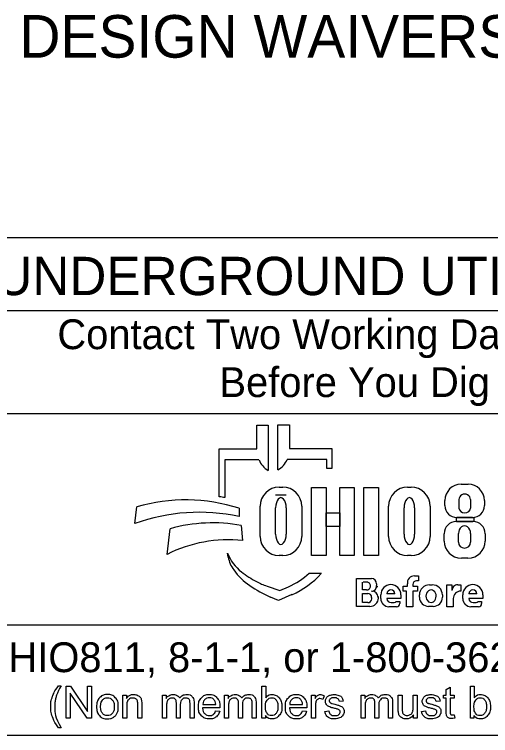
# Model space of a CAD drawing. Extents: x 0 to 34, y 0 to 22.
# Drawn here: x 2.596 to 4.831, y 2.143 to 5.529 of the extents above; entities that cross this region are included whole.
import ezdxf

# ---------------------------------------------------------------- set-up
doc = ezdxf.new("R2010")
doc.units = 0
doc.layers.add('SH_Data', color=7, linetype='Continuous')
doc.layers.add('SH_Text', color=7, linetype='Continuous')

msp = doc.modelspace()

# ---------------------------------------------------------------- linework, layer by layer
at = {"layer": 'SH_Data'}
for p, q in [((6.6275, 4.4803), (2.3775, 4.4803)), ((2.3775, 4.1387), (6.6275, 4.1387)), ((2.3775, 3.6553), (6.6275, 3.6553)), ((6.6275, 2.6607), (2.3775, 2.6607)), ((6.6275, 2.1428), (2.3775, 2.1428))]:
    msp.add_line(p, q, dxfattribs=at)
at = {"layer": 'SH_Text'}
for p, q in [((3.7335, 3.4883), (3.7335, 3.5998)), ((3.7335, 3.5998), (3.7872, 3.5998)), ((3.7872, 3.5998), (3.7872, 3.3877)), ((3.8329, 3.39), (3.8329, 3.6021)), ((3.8329, 3.6021), (3.8865, 3.6021)), ((3.8865, 3.6021), (3.8865, 3.4906)), ((3.5576, 3.2644), (3.5576, 3.4883)), ((3.5576, 3.4883), (3.7335, 3.4883)), ((3.8865, 3.4906), (4.0857, 3.4906)), ((4.0857, 3.4906), (4.0857, 3.3968)), ((3.5828, 3.4369), (3.5828, 3.26)), ((3.7439, 3.4369), (3.5828, 3.4369)), ((4.0625, 3.4392), (3.8761, 3.4392)), ((4.0625, 3.3968), (4.0625, 3.4392)), ((4.0857, 3.3968), (4.0625, 3.3968)), ((4.6931, 3.3231), (4.7258, 3.3231)), ((3.8385, 3.3091), (3.8551, 3.3091)), ((4.4416, 3.3091), (4.4581, 3.3091)), ((3.8718, 3.2721), (3.822, 3.2721)), ((4.683, 3.2111), (4.683, 3.2504)), ((4.7371, 3.2504), (4.7371, 3.2111)), ((3.7491, 3.0776), (3.7491, 3.2196)), ((3.9445, 3.2196), (3.9445, 3.0776)), ((4.3521, 3.0776), (4.3521, 3.2196)), ((4.5476, 3.2196), (4.5476, 3.0776)), ((4.6168, 3.2225), (4.6168, 3.2468)), ((4.8022, 3.2468), (4.8022, 3.2225)), ((3.1602, 3.1381), (3.1696, 3.2162)), ((3.6509, 3.2097), (3.6509, 3.1709)), ((3.822, 3.089), (3.822, 3.2114)), ((3.8718, 3.2114), (3.8718, 3.089)), ((4.425, 3.089), (4.425, 3.2114)), ((4.4748, 3.2114), (4.4748, 3.089)), ((4.7462, 3.1665), (4.6728, 3.1665)), ((3.6608, 3.1291), (3.6671, 3.0582)), ((4.671, 3.1482), (4.7483, 3.1482)), ((3.312, 2.9936), (3.3267, 3.1137)), ((4.6131, 3.0563), (4.6131, 3.0903)), ((4.6806, 3.0503), (4.6806, 3.0912)), ((4.7374, 3.0912), (4.7374, 3.0503)), ((4.8062, 3.0903), (4.8062, 3.0563)), ((3.5997, 2.9807), (3.5967, 2.9986)), ((3.8551, 2.9882), (3.8385, 2.9882)), ((4.4581, 2.9882), (4.4416, 2.9882)), ((4.7252, 2.9753), (4.6941, 2.9753)), ((3.98, 2.9048), (4.0375, 2.9048)), ((4.2013, 2.749), (4.2013, 2.8798)), ((4.2013, 2.8798), (4.2725, 2.8798)), ((4.4739, 2.8926), (4.4934, 2.8926)), ((4.4934, 2.8926), (4.4934, 2.8696)), ((3.7816, 2.8444), (3.841, 2.8239)), ((4.2293, 2.8263), (4.2293, 2.8632)), ((4.2545, 2.8632), (4.2332, 2.8632)), ((4.2963, 2.856), (4.2963, 2.8481)), ((4.4213, 2.8212), (4.4213, 2.8442)), ((4.4213, 2.8442), (4.4406, 2.8442)), ((4.4406, 2.8442), (4.4406, 2.8546)), ((4.4667, 2.8526), (4.4667, 2.8442)), ((4.4667, 2.8442), (4.4883, 2.8442)), ((4.4934, 2.8691), (4.4832, 2.8691)), ((4.4883, 2.8442), (4.4883, 2.8212)), ((4.5451, 2.8508), (4.5573, 2.8508)), ((4.6254, 2.7478), (4.6254, 2.8505)), ((4.6254, 2.8505), (4.6499, 2.8505)), ((4.6499, 2.8505), (4.6499, 2.8237)), ((4.6772, 2.8505), (4.691, 2.8505)), ((4.691, 2.8505), (4.691, 2.8209)), ((3.841, 2.8239), (3.8821, 2.8417)), ((4.2487, 2.8263), (4.2293, 2.8263)), ((4.4362, 2.8212), (4.4213, 2.8212)), ((4.4362, 2.7478), (4.4362, 2.8212)), ((4.4883, 2.8212), (4.4667, 2.8212)), ((4.4667, 2.8212), (4.4667, 2.7478)), ((3.835, 2.7769), (3.7976, 2.7934)), ((3.8983, 2.8044), (3.835, 2.7769)), ((4.2293, 2.7669), (4.2293, 2.8097)), ((4.2293, 2.8097), (4.2548, 2.8097)), ((4.2729, 2.7916), (4.2729, 2.7853)), ((4.3043, 2.7887), (4.3043, 2.7884)), ((4.3159, 2.7858), (4.3159, 2.8042)), ((4.3824, 2.8082), (4.3439, 2.8082)), ((4.4104, 2.7866), (4.344, 2.7866)), ((4.4104, 2.8042), (4.4104, 2.7866)), ((4.4973, 2.7922), (4.4973, 2.8029)), ((4.6051, 2.8029), (4.6051, 2.7922)), ((4.6559, 2.786), (4.6559, 2.7478)), ((4.7008, 2.7858), (4.7008, 2.8042)), ((4.7674, 2.8082), (4.7288, 2.8082)), ((4.7953, 2.7866), (4.7289, 2.7866)), ((4.7953, 2.8042), (4.7953, 2.7866)), ((4.265, 2.749), (4.2013, 2.749)), ((4.2546, 2.7669), (4.2293, 2.7669)), ((4.3892, 2.7478), (4.3538, 2.7478)), ((4.3649, 2.7673), (4.379, 2.7673)), ((4.3876, 2.7729), (4.4045, 2.7729)), ((4.4045, 2.7729), (4.4045, 2.7631)), ((4.4667, 2.7478), (4.4362, 2.7478)), ((4.5623, 2.7494), (4.5401, 2.7494)), ((4.6559, 2.7478), (4.6254, 2.7478)), ((4.7742, 2.7478), (4.7388, 2.7478)), ((4.7498, 2.7673), (4.7639, 2.7673)), ((4.7725, 2.7729), (4.7894, 2.7729)), ((4.7894, 2.7729), (4.7894, 2.7631))]:
    msp.add_line(p, q, dxfattribs=at)
for points in [[(3.991, 3.3081), (4.0589, 3.3081), (4.0589, 2.9881), (3.991, 2.9881)], [(4.1231, 3.3081), (4.1911, 3.3081), (4.1911, 2.9881), (4.1231, 2.9881)], [(4.2364, 3.3081), (4.3052, 3.3081), (4.3052, 2.9881), (4.2364, 2.9881)], [(4.0589, 3.1882), (4.1231, 3.1882), (4.1231, 3.1242), (4.0589, 3.1242)], [(4.6706, 3.1665), (4.7523, 3.1665), (4.7523, 3.1481), (4.6706, 3.1481)]]:
    msp.add_lwpolyline(points, close=True, dxfattribs=at)
for points in [[(2.8021, 2.3766), (2.8153, 2.3766)], [(2.8389, 2.2239), (2.8389, 2.3741), (2.8592, 2.3741), (2.9382, 2.2561), (2.9382, 2.3741), (2.9572, 2.3741), (2.9572, 2.2239), (2.9369, 2.2239), (2.8579, 2.3419), (2.8579, 2.2239), (2.8389, 2.2239)], [(3.7743, 2.2239), (3.7573, 2.2239), (3.7573, 2.3741), (3.7757, 2.3741), (3.7757, 2.3206)], [(4.6233, 2.2558), (4.6233, 2.3185), (4.6097, 2.3185), (4.6097, 2.3328), (4.6233, 2.3328), (4.6233, 2.3597), (4.6417, 2.3708), (4.6417, 2.3328), (4.6601, 2.3328), (4.6601, 2.3185), (4.6417, 2.3185), (4.6417, 2.2547)], [(4.7534, 2.2239), (4.7363, 2.2239), (4.7363, 2.3741), (4.7548, 2.3741), (4.7548, 2.3206)], [(3.1048, 2.2239), (3.1048, 2.3328), (3.1214, 2.3328), (3.1214, 2.3173)], [(3.2912, 2.2239), (3.2912, 2.3328), (3.3077, 2.3328), (3.3077, 2.3174)], [(3.5826, 2.2239), (3.5826, 2.3328), (3.5991, 2.3328), (3.5991, 2.3174)], [(3.9904, 2.2239), (3.9904, 2.3328), (4.007, 2.3328), (4.007, 2.3163)], [(4.0495, 2.3293), (4.043, 2.3122)], [(4.1394, 2.3046), (4.1213, 2.3022)], [(4.2236, 2.2239), (4.2236, 2.3328), (4.2401, 2.3328), (4.2401, 2.3174)], [(4.3979, 2.2654), (4.3979, 2.3328), (4.4164, 2.3328), (4.4164, 2.2724)], [(4.4676, 2.2745), (4.4676, 2.3328), (4.4861, 2.3328), (4.4861, 2.2239), (4.4696, 2.2239)], [(4.594, 2.3046), (4.5759, 2.3022)], [(3.1233, 2.2833), (3.1233, 2.2239), (3.1048, 2.2239)], [(3.1932, 2.2908), (3.1932, 2.2239), (3.1748, 2.2239), (3.1748, 2.2901)], [(3.3097, 2.2803), (3.3097, 2.2239), (3.2912, 2.2239)], [(3.3743, 2.2871), (3.3743, 2.2239), (3.3559, 2.2239), (3.3559, 2.2946)], [(3.4388, 2.2986), (3.4388, 2.2239), (3.4203, 2.2239), (3.4203, 2.2924)], [(3.56, 2.2736), (3.4788, 2.2736)], [(3.4799, 2.2887), (3.5406, 2.2887)], [(3.601, 2.2803), (3.601, 2.2239), (3.5826, 2.2239)], [(3.6657, 2.2871), (3.6657, 2.2239), (3.6473, 2.2239), (3.6473, 2.2946)], [(3.7301, 2.2986), (3.7301, 2.2239), (3.7117, 2.2239), (3.7117, 2.2924)], [(3.968, 2.2736), (3.8868, 2.2736)], [(3.8879, 2.2887), (3.9486, 2.2887)], [(4.0088, 2.2809), (4.0088, 2.2239), (3.9904, 2.2239)], [(4.242, 2.2803), (4.242, 2.2239), (4.2236, 2.2239)], [(4.3067, 2.2871), (4.3067, 2.2239), (4.2883, 2.2239), (4.2883, 2.2946)], [(4.3711, 2.2986), (4.3711, 2.2239), (4.3527, 2.2239), (4.3527, 2.2924)], [(3.5404, 2.2591), (3.5595, 2.2567)], [(3.7743, 2.2375), (3.7743, 2.2239)], [(3.9484, 2.2591), (3.9675, 2.2567)], [(4.053, 2.2564), (4.0712, 2.2593)], [(4.4696, 2.2239), (4.4696, 2.24)], [(4.5076, 2.2564), (4.5258, 2.2593)], [(4.6601, 2.2404), (4.6628, 2.2241)], [(4.7534, 2.2375), (4.7534, 2.2239)], [(2.8153, 2.1798), (2.8021, 2.1798)]]:
    msp.add_lwpolyline(points, dxfattribs=at)
for centre, radius, start, end in [((3.8353, 3.4736), 0.0985, 201.9296, 240.7469), ((3.7847, 3.476), 0.0985, 299.2531, 338.0704), ((4.6931, 3.2468), 0.0763, 90, 180), ((4.7258, 3.2468), 0.0763, 0, 90), ((3.8385, 3.2196), 0.0895, 90, 180), ((3.8551, 3.2196), 0.0895, 0, 90), ((4.4416, 3.2196), 0.0895, 90, 180), ((4.4581, 3.2196), 0.0895, 0, 90), ((3.4295, 2.4554), 0.8191, 79.2074, 81.0007), ((3.3997, 2.4302), 0.8191, 72.1402, 106.3144), ((4.6728, 3.2225), 0.056, 180, 270), ((4.7462, 3.2225), 0.056, 270, 0), ((3.4628, 2.2991), 0.8919, 77.8238, 109.8274), ((3.5267, 2.4094), 0.7322, 79.44, 105.8467), ((4.671, 3.0903), 0.0579, 90, 180), ((4.7483, 3.0903), 0.0579, 0, 90), ((3.5987, 2.4262), 0.6357, 83.8248, 116.8021), ((3.8385, 3.0776), 0.0895, 180, 270), ((3.8551, 3.0776), 0.0895, 270, 0), ((4.4416, 3.0776), 0.0895, 180, 270), ((4.4581, 3.0776), 0.0895, 270, 0), ((4.6941, 3.0563), 0.081, 180, 270), ((4.7252, 3.0563), 0.081, 270, 0), ((3.7841, 3.0707), 0.2008, 201.0457, 232.5314), ((3.741, 3.0048), 0.1433, 189.6817, 216.0884), ((3.8747, 3.1022), 0.3088, 216.0884, 235.7167), ((3.9766, 3.3219), 0.5173, 232.5314, 241.794), ((3.7387, 3.1722), 0.3602, 293.4582, 312.0712), ((3.7387, 3.1722), 0.401, 293.4582, 317.8286), ((4.2725, 2.856), 0.0238, 0, 90), ((4.4739, 2.859), 0.0335, 90, 187.5187), ((4.0412, 3.3465), 0.6044, 235.7167, 246.2325), ((3.8914, 3.1631), 0.3371, 241.794, 250.9821), ((4.2487, 2.845), 0.0187, 270, 2.0582), ((4.2505, 2.8463), 0.0169, 357.8325, 90), ((4.2721, 2.8453), 0.0243, 270, 6.6529), ((4.3631, 2.8042), 0.0473, 0, 180), ((4.4832, 2.8526), 0.0165, 90, 180), ((4.5451, 2.8029), 0.0478, 90, 180), ((4.5573, 2.8029), 0.0478, 0, 90), ((4.6768, 2.8237), 0.0269, 89.2449, 180), ((4.7481, 2.8042), 0.0473, 0, 180), ((4.2722, 2.7889), 0.0321, 4.0748, 90), ((4.2827, 2.8438), 0.0175, 347.4023, 0), ((4.3632, 2.8072), 0.0193, 2.9632, 177.0368), ((4.6908, 2.786), 0.0349, 89.6033, 180), ((4.7481, 2.8072), 0.0193, 2.9632, 177.0368), ((4.2546, 2.7853), 0.0184, 270, 0), ((4.2548, 2.7916), 0.0181, 0, 90), ((4.265, 2.7884), 0.0393, 270, 0), ((4.2714, 2.7887), 0.033, 0, 11.7502), ((4.3538, 2.7858), 0.038, 180, 270), ((4.3649, 2.7883), 0.021, 184.827, 270), ((4.5401, 2.7922), 0.0428, 180, 270), ((4.5623, 2.7922), 0.0428, 270, 0), ((4.7388, 2.7858), 0.038, 180, 270), ((4.7498, 2.7883), 0.021, 184.827, 270), ((4.379, 2.7767), 0.00938, 270, 335.9979), ((4.3892, 2.7631), 0.0152, 270, 0), ((4.7639, 2.7767), 0.00938, 270, 335.9979), ((4.7742, 2.7631), 0.0152, 270, 0)]:
    msp.add_arc(centre, radius, start, end, dxfattribs=at)
for centre, major_axis, ratio, start_param, end_param in [((3.8469, 3.2114), (0, 0.0484), 0.514403, 4.712389, 7.853982), ((4.4499, 3.2114), (0, 0.0484), 0.514403, 4.712389, 7.853982), ((4.71, 3.2504), (0.0271, 0), 0.969373, 0, 3.141593), ((4.71, 3.2111), (0.0271, 0), 0.818453, 3.141593, 6.283185), ((4.709, 3.0912), (0, 0.0358), 0.794529, 4.712389, 7.853982), ((3.8469, 3.089), (0, 0.0484), 0.514403, 1.570796, 4.712389), ((4.4499, 3.089), (0, 0.0484), 0.514403, 1.570796, 4.712389), ((4.709, 3.0503), (0.0284, 0), 0.959837, 3.141593, 6.283185), ((4.5517, 2.7976), (0, 0.029), 0.832186, 4.712389, 7.853982), ((4.5517, 2.7976), (0, 0.0302), 0.797287, 1.570796, 4.712389)]:
    msp.add_ellipse(centre, major_axis=major_axis, ratio=ratio, start_param=start_param, end_param=end_param, dxfattribs=at)
for points in [[(2.8021, 2.1798), (2.7869, 2.199), (2.7763, 2.2248), (2.7657, 2.2506), (2.7657, 2.2783), (2.7657, 2.3026), (2.7736, 2.325), (2.7829, 2.3509), (2.8021, 2.3766)], [(2.8153, 2.3766), (2.8029, 2.3553), (2.7989, 2.3462), (2.7927, 2.332), (2.7891, 2.3167), (2.7847, 2.2975), (2.7847, 2.2782), (2.7847, 2.2289), (2.8153, 2.1798)], [(2.9814, 2.2783), (2.9814, 2.3085), (2.9981, 2.3231), (3.0122, 2.3352), (3.0323, 2.3352), (3.0547, 2.3352), (3.069, 2.3205), (3.0832, 2.3058), (3.0832, 2.2799), (3.0832, 2.2589), (3.0769, 2.2469), (3.0706, 2.2348), (3.0586, 2.2282), (3.0466, 2.2215), (3.0323, 2.2215), (3.0095, 2.2215), (2.9954, 2.2362), (2.9814, 2.2508), (2.9814, 2.2783)], [(3.0003, 2.2783), (3.0003, 2.2574), (3.0094, 2.247), (3.0185, 2.2366), (3.0323, 2.2366), (3.046, 2.2366), (3.0551, 2.2471), (3.0642, 2.2575), (3.0642, 2.279), (3.0642, 2.2991), (3.0551, 2.3095), (3.0459, 2.3199), (3.0323, 2.3199), (3.0185, 2.3199), (3.0094, 2.3096), (3.0003, 2.2992), (3.0003, 2.2783)], [(3.1214, 2.3173), (3.1334, 2.3352), (3.156, 2.3352), (3.1659, 2.3352), (3.1741, 2.3316), (3.1823, 2.3281), (3.1864, 2.3224), (3.1905, 2.3166), (3.1922, 2.3087), (3.1932, 2.3036), (3.1932, 2.2908)], [(3.1748, 2.2901), (3.1748, 2.3013), (3.1726, 2.3069), (3.1705, 2.3125), (3.165, 2.3158), (3.1595, 2.3191), (3.1521, 2.3191), (3.1404, 2.3191), (3.1318, 2.3117), (3.1233, 2.3042), (3.1233, 2.2833)], [(3.3077, 2.3174), (3.3128, 2.3254), (3.3214, 2.3303), (3.3299, 2.3352), (3.3407, 2.3352), (3.3528, 2.3352), (3.3606, 2.3301), (3.3683, 2.3251), (3.3715, 2.3161), (3.3844, 2.3352), (3.4051, 2.3352), (3.4213, 2.3352), (3.43, 2.3262), (3.4388, 2.3172), (3.4388, 2.2986)], [(3.3559, 2.2946), (3.3559, 2.3069), (3.3514, 2.313), (3.3469, 2.3191), (3.3366, 2.3191), (3.3288, 2.3191), (3.3222, 2.315), (3.3156, 2.311), (3.3126, 2.3031), (3.3097, 2.2952), (3.3097, 2.2803)], [(3.4203, 2.2924), (3.4203, 2.3035), (3.4185, 2.3083), (3.4168, 2.3132), (3.412, 2.3162), (3.4073, 2.3191), (3.401, 2.3191), (3.3895, 2.3191), (3.3819, 2.3115), (3.3743, 2.3039), (3.3743, 2.2871)], [(3.5595, 2.2567), (3.555, 2.24), (3.5428, 2.2307), (3.5306, 2.2215), (3.5117, 2.2215), (3.4878, 2.2215), (3.4738, 2.2362), (3.4598, 2.2509), (3.4598, 2.2774), (3.4598, 2.3049), (3.474, 2.32), (3.4881, 2.3352), (3.5106, 2.3352), (3.5324, 2.3352), (3.5463, 2.3203), (3.5601, 2.3055), (3.5601, 2.2785), (3.5601, 2.2769), (3.56, 2.2736)], [(3.5406, 2.2887), (3.5394, 2.3025), (3.5337, 2.3094), (3.5249, 2.3201), (3.5108, 2.3201), (3.4981, 2.3201), (3.4894, 2.3115), (3.4808, 2.303), (3.4799, 2.2887)], [(3.5991, 2.3174), (3.6042, 2.3254), (3.6127, 2.3303), (3.6212, 2.3352), (3.6321, 2.3352), (3.6442, 2.3352), (3.6519, 2.3301), (3.6597, 2.3251), (3.6628, 2.3161), (3.6758, 2.3352), (3.6965, 2.3352), (3.7127, 2.3352), (3.7214, 2.3262), (3.7301, 2.3172), (3.7301, 2.2986)], [(3.6473, 2.2946), (3.6473, 2.3069), (3.6428, 2.313), (3.6383, 2.3191), (3.628, 2.3191), (3.6202, 2.3191), (3.6136, 2.315), (3.607, 2.311), (3.604, 2.3031), (3.601, 2.2952), (3.601, 2.2803)], [(3.7117, 2.2924), (3.7117, 2.3035), (3.7099, 2.3083), (3.7081, 2.3132), (3.7034, 2.3162), (3.6987, 2.3191), (3.6923, 2.3191), (3.6809, 2.3191), (3.6733, 2.3115), (3.6657, 2.3039), (3.6657, 2.2871)], [(3.7741, 2.2792), (3.7741, 2.2596), (3.7794, 2.2509), (3.7881, 2.2366), (3.8029, 2.2366), (3.815, 2.2366), (3.8238, 2.2471), (3.8326, 2.2576), (3.8326, 2.2784), (3.8326, 2.2998), (3.8241, 2.3099), (3.8157, 2.3201), (3.8038, 2.3201), (3.7917, 2.3201), (3.7829, 2.3096), (3.7741, 2.299), (3.7741, 2.2792)], [(3.7757, 2.3206), (3.7874, 2.3352), (3.8055, 2.3352), (3.8155, 2.3352), (3.8245, 2.3311), (3.8335, 2.3271), (3.8392, 2.3198), (3.845, 2.3124), (3.8483, 2.3021), (3.8516, 2.2918), (3.8516, 2.28), (3.8516, 2.252), (3.8378, 2.2368), (3.8239, 2.2215), (3.8046, 2.2215), (3.7853, 2.2215), (3.7743, 2.2375)], [(3.9675, 2.2567), (3.963, 2.24), (3.9508, 2.2307), (3.9386, 2.2215), (3.9196, 2.2215), (3.8958, 2.2215), (3.8818, 2.2362), (3.8678, 2.2509), (3.8678, 2.2774), (3.8678, 2.3049), (3.882, 2.32), (3.8961, 2.3352), (3.9186, 2.3352), (3.9404, 2.3352), (3.9543, 2.3203), (3.9681, 2.3055), (3.9681, 2.2785), (3.9681, 2.2769), (3.968, 2.2736)], [(3.9486, 2.2887), (3.9474, 2.3025), (3.9417, 2.3094), (3.9328, 2.3201), (3.9188, 2.3201), (3.9061, 2.3201), (3.8974, 2.3115), (3.8888, 2.303), (3.8879, 2.2887)], [(4.007, 2.3163), (4.0133, 2.3278), (4.0187, 2.3315), (4.0241, 2.3352), (4.0305, 2.3352), (4.0398, 2.3352), (4.0495, 2.3293)], [(4.043, 2.3122), (4.0363, 2.3162), (4.0295, 2.3162), (4.0235, 2.3162), (4.0187, 2.3125), (4.0139, 2.3089), (4.0119, 2.3024), (4.0088, 2.2926), (4.0088, 2.2809)], [(4.1213, 2.3022), (4.1201, 2.3106), (4.1142, 2.3153), (4.1083, 2.3201), (4.0975, 2.3201), (4.0848, 2.3201), (4.0794, 2.3159), (4.0739, 2.3116), (4.0739, 2.306), (4.0739, 2.3024), (4.0762, 2.2995), (4.0785, 2.2966), (4.0833, 2.2946), (4.086, 2.2936), (4.0996, 2.2899), (4.1192, 2.2847), (4.1269, 2.2813), (4.1347, 2.278), (4.1391, 2.2717), (4.1435, 2.2653), (4.1435, 2.2559), (4.1435, 2.2467), (4.1381, 2.2386), (4.1327, 2.2304), (4.1226, 2.226), (4.1124, 2.2215), (4.0996, 2.2215), (4.0784, 2.2215), (4.0672, 2.2303), (4.0561, 2.2391), (4.053, 2.2564)], [(4.0712, 2.2593), (4.0727, 2.2483), (4.0798, 2.2425), (4.0868, 2.2366), (4.0995, 2.2366), (4.1122, 2.2366), (4.1184, 2.2418), (4.1245, 2.247), (4.1245, 2.254), (4.1245, 2.2602), (4.1191, 2.2638), (4.1153, 2.2663), (4.1002, 2.2701), (4.0799, 2.2752), (4.072, 2.2789), (4.0642, 2.2827), (4.0601, 2.2893), (4.0561, 2.2959), (4.0561, 2.3038), (4.0561, 2.3111), (4.0594, 2.3173), (4.0628, 2.3235), (4.0685, 2.3276), (4.0728, 2.3308), (4.0803, 2.333), (4.0877, 2.3352), (4.0962, 2.3352), (4.109, 2.3352), (4.1187, 2.3315), (4.1284, 2.3278), (4.133, 2.3215), (4.1377, 2.3152), (4.1394, 2.3046)], [(4.2401, 2.3174), (4.2452, 2.3254), (4.2537, 2.3303), (4.2622, 2.3352), (4.2731, 2.3352), (4.2852, 2.3352), (4.2929, 2.3301), (4.3007, 2.3251), (4.3038, 2.3161), (4.3168, 2.3352), (4.3375, 2.3352), (4.3537, 2.3352), (4.3624, 2.3262), (4.3711, 2.3172), (4.3711, 2.2986)], [(4.2883, 2.2946), (4.2883, 2.3069), (4.2838, 2.313), (4.2793, 2.3191), (4.269, 2.3191), (4.2612, 2.3191), (4.2546, 2.315), (4.248, 2.311), (4.245, 2.3031), (4.242, 2.2952), (4.242, 2.2803)], [(4.3527, 2.2924), (4.3527, 2.3035), (4.3509, 2.3083), (4.3491, 2.3132), (4.3444, 2.3162), (4.3397, 2.3191), (4.3333, 2.3191), (4.3219, 2.3191), (4.3143, 2.3115), (4.3067, 2.3039), (4.3067, 2.2871)], [(4.5759, 2.3022), (4.5747, 2.3106), (4.5688, 2.3153), (4.5629, 2.3201), (4.5521, 2.3201), (4.5394, 2.3201), (4.5339, 2.3159), (4.5285, 2.3116), (4.5285, 2.306), (4.5285, 2.3024), (4.5308, 2.2995), (4.533, 2.2966), (4.5378, 2.2946), (4.5406, 2.2936), (4.5542, 2.2899), (4.5737, 2.2847), (4.5815, 2.2813), (4.5893, 2.278), (4.5937, 2.2717), (4.5981, 2.2653), (4.5981, 2.2559), (4.5981, 2.2467), (4.5927, 2.2386), (4.5873, 2.2304), (4.5772, 2.226), (4.567, 2.2215), (4.5542, 2.2215), (4.5329, 2.2215), (4.5218, 2.2303), (4.5107, 2.2391), (4.5076, 2.2564)], [(4.5258, 2.2593), (4.5273, 2.2483), (4.5343, 2.2425), (4.5414, 2.2366), (4.554, 2.2366), (4.5668, 2.2366), (4.5729, 2.2418), (4.5791, 2.247), (4.5791, 2.254), (4.5791, 2.2602), (4.5736, 2.2638), (4.5698, 2.2663), (4.5548, 2.2701), (4.5345, 2.2752), (4.5266, 2.2789), (4.5188, 2.2827), (4.5147, 2.2893), (4.5107, 2.2959), (4.5107, 2.3038), (4.5107, 2.3111), (4.514, 2.3173), (4.5173, 2.3235), (4.5231, 2.3276), (4.5274, 2.3308), (4.5348, 2.333), (4.5423, 2.3352), (4.5508, 2.3352), (4.5636, 2.3352), (4.5733, 2.3315), (4.583, 2.3278), (4.5876, 2.3215), (4.5922, 2.3152), (4.594, 2.3046)], [(4.7532, 2.2792), (4.7532, 2.2596), (4.7585, 2.2509), (4.7672, 2.2366), (4.782, 2.2366), (4.7941, 2.2366), (4.8029, 2.2471), (4.8116, 2.2576), (4.8116, 2.2784), (4.8116, 2.2998), (4.8032, 2.3099), (4.7948, 2.3201), (4.7828, 2.3201), (4.7708, 2.3201), (4.762, 2.3096), (4.7532, 2.299), (4.7532, 2.2792)], [(4.7548, 2.3206), (4.7664, 2.3352), (4.7846, 2.3352), (4.7946, 2.3352), (4.8036, 2.3311), (4.8125, 2.3271), (4.8183, 2.3198), (4.8241, 2.3124), (4.8274, 2.3021), (4.8306, 2.2918), (4.8306, 2.28), (4.8306, 2.252), (4.8168, 2.2368), (4.803, 2.2215), (4.7836, 2.2215), (4.7644, 2.2215), (4.7534, 2.2375)], [(3.4788, 2.2736), (3.4799, 2.2557), (3.489, 2.2462), (3.4981, 2.2366), (3.5117, 2.2366), (3.5219, 2.2366), (3.5291, 2.242), (3.5362, 2.2473), (3.5404, 2.2591)], [(3.8868, 2.2736), (3.8879, 2.2557), (3.897, 2.2462), (3.9061, 2.2366), (3.9197, 2.2366), (3.9299, 2.2366), (3.937, 2.242), (3.9442, 2.2473), (3.9484, 2.2591)], [(4.4164, 2.2724), (4.4164, 2.258), (4.4175, 2.253), (4.4192, 2.2457), (4.4249, 2.2416), (4.4305, 2.2374), (4.4388, 2.2374), (4.4471, 2.2374), (4.4543, 2.2417), (4.4616, 2.2459), (4.4646, 2.2533), (4.4676, 2.2606), (4.4676, 2.2745)], [(4.4696, 2.24), (4.4569, 2.2215), (4.4351, 2.2215), (4.4255, 2.2215), (4.4171, 2.2252), (4.4088, 2.2289), (4.4047, 2.2345), (4.4007, 2.2401), (4.3991, 2.2482), (4.3979, 2.2536), (4.3979, 2.2654)], [(4.6628, 2.2241), (4.655, 2.2224), (4.6488, 2.2224), (4.6388, 2.2224), (4.6333, 2.2256), (4.6278, 2.2288), (4.6255, 2.234), (4.6233, 2.2392), (4.6233, 2.2558)], [(4.6417, 2.2547), (4.6417, 2.2468), (4.6427, 2.2445), (4.6436, 2.2423), (4.6458, 2.2409), (4.648, 2.2396), (4.6521, 2.2396), (4.6551, 2.2396), (4.6601, 2.2404)]]:
    msp.add_open_spline(points, degree=3, dxfattribs=at)

# ---------------------------------------------------------------- texts
for s, height, p in [('ADA DESIGN WAIVERS', 0.2, (1.9944, 5.3256)), ('UNDERGROUND UTILITIES', 0.18, (2.5057, 4.2106)), ('Contact Two Working Days', 0.14, (2.7972, 3.9571)), ('Before You Dig', 0.14, (3.5583, 3.7321)), ('OHIO811, 8-1-1, or 1-800-362-2764', 0.14, (2.422, 2.4406))]:
    msp.add_text(s, height=height, dxfattribs=at).set_placement(p)

doc.saveas('drawing.dxf')
